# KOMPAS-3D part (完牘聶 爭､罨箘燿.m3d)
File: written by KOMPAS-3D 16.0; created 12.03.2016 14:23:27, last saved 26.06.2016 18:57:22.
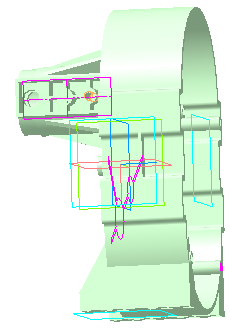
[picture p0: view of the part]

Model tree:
1. Эскиз:1
2. Операция выдавливания:1
     Расстояние 1 = 48
3. Оболочка:1
     Толщина стенки 2 = 3
4. Эскиз:2
5. Операция выдавливания:2
     Расстояние 1 = 46
6. Эскиз:3
7. Вырезать элемент выдавливания:1
     Расстояние 1 = 40
8. Эскиз:4
9. Вырезать элемент выдавливания:2
     Расстояние 1 = 40
10. Эскиз:5
11. Эскиз:6
12. Скругление:1
     Радиус = 2
13. Скругление:2
     Радиус = 2
14. Скругление:3
     Радиус = 2
15. Эскиз:10
16. Операция выдавливания:5
     Расстояние 1 = 56
17. Эскиз:11
18. Вырезать элемент выдавливания:6
     Расстояние 1 = 10
19. Эскиз:12
20. Операция выдавливания:6
     Расстояние 1 = 40; Расстояние 2 = 3
21. Массив по концентрической сетке:1  (with: Операция выдавливания:6, Эскиз:12)  (8 pattern instances)
     Геометрический массив = 7; Шаг 2 = 360
22. Смещенная плоскость:1
     Расстояние = 20
23. Эскиз:13
24. Операция выдавливания:7
     Расстояние 1 = 40; Расстояние 2 = 22
25. Операция выдавливания:8
     Расстояние 1 = 78; Расстояние 2 = 38
26. Эскиз:8
27. Эскиз:14
28. Вырезать элемент выдавливания:7
     Расстояние 1 = 10
29. Эскиз:15
30. Вырезать элемент выдавливания:8
     Расстояние 1 = 30
31. Эскиз:16
32. Вырезать элемент выдавливания:9
     Расстояние 1 = 80
33. Эскиз:17
34. Вырезать элемент выдавливания:10
     Расстояние 1 = 10
35. Эскиз:18
36. Вырезать элемент выдавливания:11
     Расстояние 1 = 20
37. Эскиз:19
38. Вырезать элемент выдавливания:12
     Расстояние 1 = 9
39. Эскиз:20
40. Операция выдавливания:9
     Расстояние 1 = 10; Расстояние 2 = 38
41. Фаска:1
     Угол = 22; Длина 1 = 24; Длина 2 = 9.69663
42. Фаска:2
     Угол = 22; Длина 1 = 21; Длина 2 = 8.48455
43. Эскиз:21
44. Вырезать элемент выдавливания:13
     Расстояние 1 = 9
45. Эскиз:22
46. Вырезать элемент выдавливания:14
     Расстояние 1 = 69
47. Эскиз:23
48. Эскиз:25
49. Операция выдавливания:10
     Расстояние 1 = 2; Расстояние 2 = 38
50. Эскиз:26
51. Вырезать элемент выдавливания:16
     Расстояние 1 = 69
52. Эскиз:27
53. Операция выдавливания:11
     Расстояние 1 = 10; Расстояние 2 = 38
54. Фаска:3
     Угол = 68; Длина 1 = 4; Длина 2 = 9.90035
55. Фаска:4
     Угол = 68; Длина 1 = 4; Длина 2 = 9.90035
56. Фаска:5
     Угол = 68; Длина 1 = 4; Длина 2 = 9.90035
57. Эскиз:28
58. Вырезать элемент выдавливания:17
     Расстояние 1 = 69
59. Смещенная плоскость:2
     Расстояние = 48
60. Эскиз:29
61. Операция выдавливания:12
     Расстояние 1 = 10; Расстояние 2 = 65
62. Эскиз:30
63. Вырезать элемент выдавливания:20
     Расстояние 2 = 20; Расстояние 1 = 16.8449
64. Эскиз:32
65. Вырезать элемент выдавливания:21
     Расстояние 1 = 17
66. Фаска:7
     Угол = 60; Длина 1 = 17; Длина 2 = 29.4449
67. Скругление:8
     Полуось 1 = 6.0001; Полуось 2 = 15
68. Вырезать элемент выдавливания:25
     Расстояние 1 = 10
69. Смещенная плоскость:4
     Расстояние = 87
70. Эскиз:36
71. Операция выдавливания:13
     Расстояние 1 = 7
72. Операция выдавливания:16
     Расстояние 1 = 5
73. Операция выдавливания:17
     Расстояние 1 = 5
74. Эскиз:37
75. Операция выдавливания:18
     Расстояние 1 = 7
76. Операция выдавливания:19
     Расстояние 1 = 5
77. Операция выдавливания:20
     Расстояние 1 = 5
78. Эскиз:38
79. Операция выдавливания:21
     Расстояние 1 = 9.32752
80. Операция выдавливания:22
     Расстояние 1 = 1.66005
81. Операция выдавливания:23
     Расстояние 1 = 2.56669
82. Вырезать элемент выдавливания:26
     Расстояние 1 = 40
83. Вырезать элемент выдавливания:27
     Расстояние 1 = 40
84. Условное изображение резьбы:1  (labels: E:\Sys\Thread\cil0_8724-2002 coarse.xml; M5)
     Длина резьбы = 16; Шаг резьбы = 0.8; Номинальный диаметр резьбы = 5
85. Подгонка:1
86. Операция выдавливания:27
     Расстояние 1 = 4.09054; Расстояние 2 = 65
87. Операция выдавливания:28
     Расстояние 1 = 4.09054; Расстояние 2 = 65
88. Вырезать элемент выдавливания:33
     Расстояние 2 = 20; Расстояние 1 = 1
89. Фаска:9
     Угол = 60; Длина 1 = 17; Длина 2 = 29.4449
90. Скругление:11
     Радиус = 8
